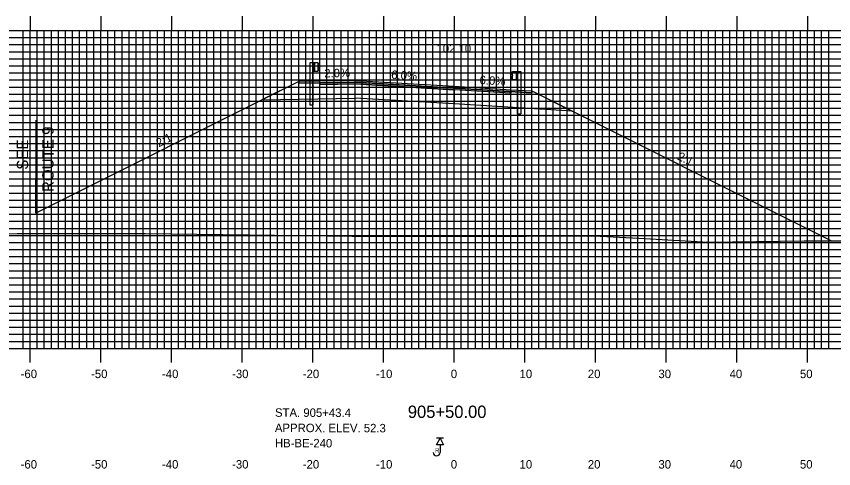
# Model space of a CAD drawing. Extents: x 857504 to 857847, y 364765 to 364985.
# Drawn here: x 857607.4 to 857723, y 364831.3 to 364895.3 of the extents above; entities that cross this region are included whole.
import ezdxf

# ---------------------------------------------------------------- set-up
doc = ezdxf.new("R2010")
doc.units = 0
for name, color, linetype in [('ANNOTATION', 7, 'Continuous'), ('BORING - REFUSAL', 7, 'Continuous'), ('D_Guardrail_Beam_Lt', 7, 'Continuous'), ('D_Guardrail_Beam_Rt', 7, 'Continuous'), ('D_Roadway_Centerline_Text', 7, 'Continuous'), ('D_Roadway_Edge_Shoulder', 7, 'Continuous'), ('D_Roadway_Edge_TW', 7, 'Continuous'), ('D_Roadway_Pavement', 7, 'Continuous'), ('D_Roadway_SlopeLines', 7, 'Continuous'), ('D_Roadway_SubGrade', 7, 'Continuous'), ('H_V ANNOTATION', 7, 'Continuous'), ('MAJOR', 7, 'Continuous'), ('MINOR', 7, 'Continuous'), ('S_Roadway_Centerline', 7, 'Continuous')]:
    doc.layers.add(name, color=color, linetype=linetype)

msp = doc.modelspace()

# ---------------------------------------------------------------- linework, layer by layer
at = {"layer": 'BORING - REFUSAL'}
for p, q in [((857667.79, 364835.6), (857666.83, 364835.6)), ((857667.31, 364834.64), (857667.31, 364833.58))]:
    msp.add_line(p, q, dxfattribs=at)
msp.add_lwpolyline([(857667.31, 364835.6), (857667.79, 364834.64), (857666.83, 364834.64)], close=True, dxfattribs=at)
msp.add_arc((857666.82, 364833.58), 0.485, 180, 0, dxfattribs=at)
at = {"layer": 'D_Guardrail_Beam_Lt'}
for p, q in [((857648.88, 364888.72), (857648.88, 364882.72)), ((857649.35, 364888.72), (857648.88, 364888.72)), ((857650.04, 364888.72), (857649.35, 364888.72)), ((857649.35, 364888.72), (857649.35, 364887.56)), ((857649.41, 364888.72), (857649.41, 364887.56)), ((857649.52, 364888.72), (857649.52, 364887.56)), ((857650.04, 364887.56), (857650.04, 364888.72)), ((857650.04, 364888.64), (857650.11, 364888.62)), ((857650.04, 364888.17), (857650.04, 364888.1)), ((857650.27, 364888.37), (857650.07, 364888.24)), ((857650.07, 364888.04), (857650.27, 364887.9)), ((857650.13, 364888.62), (857650.27, 364888.52)), ((857649.35, 364887.56), (857650.04, 364887.56)), ((857649.37, 364882.72), (857649.37, 364887.56)), ((857650.11, 364887.65), (857650.04, 364887.64)), ((857650.27, 364887.76), (857650.13, 364887.66)), ((857649.37, 364882.72), (857648.88, 364882.72)), ((857610.09, 364867.47), (857610.09, 364872.28))]:
    msp.add_line(p, q, dxfattribs=at)
for centre, major_axis, start_param, end_param in [((857650.12, 364888.17), (-0.0789, 0), 5.323254, 6.283185), ((857650.12, 364888.1), (-0.0789, 0), 6.283185, 7.243116), ((857650.1, 364888.58), (0.0417, 0), 0.959931, 1.376053), ((857650.22, 364888.45), (0.0877, 0), 5.323254, 7.243116), ((857650.1, 364887.69), (0.0417, 0), 4.907132, 5.323254), ((857650.22, 364887.83), (0.0877, 0), 5.323254, 7.243116)]:
    msp.add_ellipse(centre, major_axis=major_axis, ratio=0.995501, start_param=start_param, end_param=end_param, dxfattribs=at)
at = {"layer": 'D_Guardrail_Beam_Rt'}
for p, q in [((857677.49, 364887.4), (857677.35, 364887.3)), ((857677.35, 364887.15), (857677.54, 364887.02)), ((857677.54, 364886.82), (857677.35, 364886.68)), ((857677.58, 364887.42), (857677.5, 364887.4)), ((857677.57, 364886.95), (857677.57, 364886.88)), ((857677.58, 364887.5), (857678.27, 364887.5)), ((857677.58, 364886.34), (857677.58, 364887.5)), ((857678.1, 364887.5), (857678.1, 364886.34)), ((857678.2, 364887.5), (857678.2, 364886.34)), ((857678.27, 364887.5), (857678.74, 364887.5)), ((857678.27, 364887.5), (857678.27, 364886.34)), ((857678.74, 364887.5), (857678.74, 364881.5)), ((857677.35, 364886.54), (857677.49, 364886.44)), ((857677.5, 364886.43), (857677.58, 364886.42)), ((857678.27, 364886.34), (857677.58, 364886.34)), ((857678.25, 364881.5), (857678.25, 364886.34)), ((857678.25, 364881.5), (857678.74, 364881.5))]:
    msp.add_line(p, q, dxfattribs=at)
for centre, major_axis, start_param, end_param in [((857677.4, 364887.23), (-0.0877, 0), 5.323254, 7.243116), ((857677.51, 364887.36), (-0.0417, 0), 4.907132, 5.323254), ((857677.5, 364886.95), (0.0789, 0), 0, 0.959931), ((857677.5, 364886.88), (0.0789, 0), 5.323254, 6.283185), ((857677.4, 364886.61), (-0.0877, 0), 5.323254, 7.243116), ((857677.51, 364886.47), (-0.0417, 0), 0.959931, 1.376053)]:
    msp.add_ellipse(centre, major_axis=major_axis, ratio=0.995501, start_param=start_param, end_param=end_param, dxfattribs=at)
at = {"layer": 'D_Roadway_Edge_Shoulder'}
for points in [[(857655.31, 364886.24), (857650.31, 364886.14), (857650.31, 364886.14), (857647.31, 364886.08), (857647.31, 364885.83), (857650.31, 364885.89), (857655.31, 364885.99)], [(857669.31, 364885.4), (857677.31, 364884.92), (857677.31, 364884.92), (857680.31, 364884.74), (857680.31, 364884.49), (857669.31, 364885.15)]]:
    msp.add_lwpolyline(points, close=True, dxfattribs=at)
at = {"layer": 'D_Roadway_Edge_TW'}
msp.add_lwpolyline([(857655.31, 364886.24), (857669.31, 364885.4), (857669.31, 364885.15), (857655.31, 364885.99)], close=True, dxfattribs=at)
at = {"layer": 'D_Roadway_Pavement'}
for points in [[(857655.31, 364885.99), (857650.31, 364885.89), (857650.31, 364885.64), (857655.31, 364885.74)], [(857655.31, 364885.99), (857669.31, 364885.15), (857669.31, 364884.9), (857655.31, 364885.74)]]:
    msp.add_lwpolyline(points, close=True, dxfattribs=at)
for points in [[(857669.31, 364885.15), (857669.31, 364884.9)], [(857669.31, 364885.15), (857669.31, 364884.9)], [(857669.31, 364885.15), (857669.31, 364884.9)], [(857669.31, 364885.15), (857677.31, 364884.67), (857677.31, 364884.42), (857669.31, 364884.9)]]:
    msp.add_lwpolyline(points, dxfattribs=at)
at = {"layer": 'D_Roadway_SlopeLines'}
for points in [[(857647.31, 364886.08), (857610.09, 364867.47)], [(857680.31, 364884.74), (857722.71, 364863.54)]]:
    msp.add_lwpolyline(points, dxfattribs=at)
at = {"layer": 'D_Roadway_SubGrade'}
msp.add_line((857610.09, 364880.61), (857610.09, 364867.47), dxfattribs=at)
for points in [[(857655.31, 364885.74), (857650.31, 364885.64), (857650.31, 364885.89), (857647.31, 364885.83), (857647.31, 364886.08), (857642.1, 364883.47), (857655.31, 364883.74)], [(857655.31, 364885.74), (857669.31, 364884.9), (857669.31, 364882.9), (857655.31, 364883.74)], [(857669.31, 364884.9), (857669.31, 364885.15), (857680.31, 364884.49), (857680.31, 364884.74), (857685.99, 364881.9), (857669.31, 364882.9)]]:
    msp.add_lwpolyline(points, close=True, dxfattribs=at)
at = {"layer": 'MAJOR'}
for p, q in [((857609.31, 364895.31), (857609.31, 364893.3)), ((857619.31, 364895.31), (857619.31, 364893.3)), ((857629.31, 364895.31), (857629.31, 364893.3)), ((857639.31, 364895.31), (857639.31, 364893.3)), ((857649.31, 364895.31), (857649.31, 364893.3)), ((857659.31, 364895.31), (857659.31, 364893.3)), ((857669.31, 364895.31), (857669.31, 364893.3)), ((857679.31, 364895.31), (857679.31, 364893.3)), ((857689.31, 364895.31), (857689.31, 364893.3)), ((857699.31, 364895.31), (857699.31, 364893.3)), ((857709.31, 364895.31), (857709.31, 364893.3)), ((857719.31, 364895.31), (857719.31, 364893.3)), ((857529.31, 364893.3), (857809.31, 364893.3)), ((857529.31, 364893.3), (857809.31, 364893.3)), ((857609.31, 364848.3), (857609.31, 364893.3)), ((857619.31, 364848.3), (857619.31, 364893.3)), ((857629.31, 364848.3), (857629.31, 364893.3)), ((857639.31, 364848.3), (857639.31, 364893.3)), ((857649.31, 364848.3), (857649.31, 364893.3)), ((857659.31, 364848.3), (857659.31, 364893.3)), ((857669.31, 364848.3), (857669.31, 364893.3)), ((857679.31, 364848.3), (857679.31, 364893.3)), ((857689.31, 364848.3), (857689.31, 364893.3)), ((857699.31, 364848.3), (857699.31, 364893.3)), ((857709.31, 364848.3), (857709.31, 364893.3)), ((857719.31, 364848.3), (857719.31, 364893.3)), ((857529.31, 364888.3), (857809.31, 364888.3)), ((857529.31, 364883.3), (857809.31, 364883.3)), ((857529.31, 364878.3), (857809.31, 364878.3)), ((857529.31, 364873.3), (857809.31, 364873.3)), ((857529.31, 364868.3), (857809.31, 364868.3)), ((857529.31, 364863.3), (857809.31, 364863.3)), ((857529.31, 364858.3), (857809.31, 364858.3)), ((857529.31, 364853.3), (857809.31, 364853.3)), ((857529.31, 364848.3), (857809.31, 364848.3)), ((857529.31, 364848.3), (857809.31, 364848.3)), ((857609.31, 364846.3), (857609.31, 364848.3)), ((857619.31, 364846.3), (857619.31, 364848.3)), ((857629.31, 364846.3), (857629.31, 364848.3)), ((857639.31, 364846.3), (857639.31, 364848.3)), ((857649.31, 364846.3), (857649.31, 364848.3)), ((857659.31, 364846.3), (857659.31, 364848.3)), ((857669.31, 364846.3), (857669.31, 364848.3)), ((857679.31, 364846.3), (857679.31, 364848.3)), ((857689.31, 364846.3), (857689.31, 364848.3)), ((857699.31, 364846.3), (857699.31, 364848.3)), ((857709.31, 364846.3), (857709.31, 364848.3)), ((857719.31, 364846.3), (857719.31, 364848.3))]:
    msp.add_line(p, q, dxfattribs=at)
at = {"layer": 'MINOR'}
for p, q in [((857608.31, 364848.3), (857608.31, 364893.3)), ((857610.31, 364848.3), (857610.31, 364893.3)), ((857611.31, 364848.3), (857611.31, 364893.3)), ((857612.31, 364848.3), (857612.31, 364893.3)), ((857613.31, 364848.3), (857613.31, 364893.3)), ((857614.31, 364848.3), (857614.31, 364893.3)), ((857615.31, 364848.3), (857615.31, 364893.3)), ((857616.31, 364848.3), (857616.31, 364893.3)), ((857617.31, 364848.3), (857617.31, 364893.3)), ((857618.31, 364848.3), (857618.31, 364893.3)), ((857620.31, 364848.3), (857620.31, 364893.3)), ((857621.31, 364848.3), (857621.31, 364893.3)), ((857622.31, 364848.3), (857622.31, 364893.3)), ((857623.31, 364848.3), (857623.31, 364893.3)), ((857624.31, 364848.3), (857624.31, 364893.3)), ((857625.31, 364848.3), (857625.31, 364893.3)), ((857626.31, 364848.3), (857626.31, 364893.3)), ((857627.31, 364848.3), (857627.31, 364893.3)), ((857628.31, 364848.3), (857628.31, 364893.3)), ((857630.31, 364848.3), (857630.31, 364893.3)), ((857631.31, 364848.3), (857631.31, 364893.3)), ((857632.31, 364848.3), (857632.31, 364893.3)), ((857633.31, 364848.3), (857633.31, 364893.3)), ((857634.31, 364848.3), (857634.31, 364893.3)), ((857635.31, 364848.3), (857635.31, 364893.3)), ((857636.31, 364848.3), (857636.31, 364893.3)), ((857637.31, 364848.3), (857637.31, 364893.3)), ((857638.31, 364848.3), (857638.31, 364893.3)), ((857640.31, 364848.3), (857640.31, 364893.3)), ((857641.31, 364848.3), (857641.31, 364893.3)), ((857642.31, 364848.3), (857642.31, 364893.3)), ((857643.31, 364848.3), (857643.31, 364893.3)), ((857644.31, 364848.3), (857644.31, 364893.3)), ((857645.31, 364848.3), (857645.31, 364893.3)), ((857646.31, 364848.3), (857646.31, 364893.3)), ((857647.31, 364848.3), (857647.31, 364893.3)), ((857648.31, 364848.3), (857648.31, 364893.3)), ((857650.31, 364848.3), (857650.31, 364893.3)), ((857651.31, 364848.3), (857651.31, 364893.3)), ((857652.31, 364848.3), (857652.31, 364893.3)), ((857653.31, 364848.3), (857653.31, 364893.3)), ((857654.31, 364848.3), (857654.31, 364893.3)), ((857655.31, 364848.3), (857655.31, 364893.3)), ((857656.31, 364848.3), (857656.31, 364893.3)), ((857657.31, 364848.3), (857657.31, 364893.3)), ((857658.31, 364848.3), (857658.31, 364893.3)), ((857660.31, 364848.3), (857660.31, 364893.3)), ((857661.31, 364848.3), (857661.31, 364893.3)), ((857662.31, 364848.3), (857662.31, 364893.3)), ((857663.31, 364848.3), (857663.31, 364893.3)), ((857664.31, 364848.3), (857664.31, 364893.3)), ((857665.31, 364848.3), (857665.31, 364893.3)), ((857666.31, 364848.3), (857666.31, 364893.3)), ((857667.31, 364848.3), (857667.31, 364893.3)), ((857668.31, 364848.3), (857668.31, 364893.3)), ((857670.31, 364848.3), (857670.31, 364893.3)), ((857671.31, 364848.3), (857671.31, 364893.3)), ((857672.31, 364848.3), (857672.31, 364893.3)), ((857673.31, 364848.3), (857673.31, 364893.3)), ((857674.31, 364848.3), (857674.31, 364893.3)), ((857675.31, 364848.3), (857675.31, 364893.3)), ((857676.31, 364848.3), (857676.31, 364893.3)), ((857677.31, 364848.3), (857677.31, 364893.3)), ((857678.31, 364848.3), (857678.31, 364893.3)), ((857680.31, 364848.3), (857680.31, 364893.3)), ((857681.31, 364848.3), (857681.31, 364893.3)), ((857682.31, 364848.3), (857682.31, 364893.3)), ((857683.31, 364848.3), (857683.31, 364893.3)), ((857684.31, 364848.3), (857684.31, 364893.3)), ((857685.31, 364848.3), (857685.31, 364893.3)), ((857686.31, 364848.3), (857686.31, 364893.3)), ((857687.31, 364848.3), (857687.31, 364893.3)), ((857688.31, 364848.3), (857688.31, 364893.3)), ((857690.31, 364848.3), (857690.31, 364893.3)), ((857691.31, 364848.3), (857691.31, 364893.3)), ((857692.31, 364848.3), (857692.31, 364893.3)), ((857693.31, 364848.3), (857693.31, 364893.3)), ((857694.31, 364848.3), (857694.31, 364893.3)), ((857695.31, 364848.3), (857695.31, 364893.3)), ((857696.31, 364848.3), (857696.31, 364893.3)), ((857697.31, 364848.3), (857697.31, 364893.3)), ((857698.31, 364848.3), (857698.31, 364893.3)), ((857700.31, 364848.3), (857700.31, 364893.3)), ((857701.31, 364848.3), (857701.31, 364893.3)), ((857702.31, 364848.3), (857702.31, 364893.3)), ((857703.31, 364848.3), (857703.31, 364893.3)), ((857704.31, 364848.3), (857704.31, 364893.3)), ((857705.31, 364848.3), (857705.31, 364893.3)), ((857706.31, 364848.3), (857706.31, 364893.3)), ((857707.31, 364848.3), (857707.31, 364893.3)), ((857708.31, 364848.3), (857708.31, 364893.3)), ((857710.31, 364848.3), (857710.31, 364893.3)), ((857711.31, 364848.3), (857711.31, 364893.3)), ((857712.31, 364848.3), (857712.31, 364893.3)), ((857713.31, 364848.3), (857713.31, 364893.3)), ((857714.31, 364848.3), (857714.31, 364893.3)), ((857715.31, 364848.3), (857715.31, 364893.3)), ((857716.31, 364848.3), (857716.31, 364893.3)), ((857717.31, 364848.3), (857717.31, 364893.3)), ((857718.31, 364848.3), (857718.31, 364893.3)), ((857720.31, 364848.3), (857720.31, 364893.3)), ((857721.31, 364848.3), (857721.31, 364893.3)), ((857722.31, 364848.3), (857722.31, 364893.3)), ((857529.31, 364892.3), (857809.31, 364892.3)), ((857529.31, 364891.3), (857809.31, 364891.3)), ((857529.31, 364890.3), (857809.31, 364890.3)), ((857529.31, 364889.3), (857809.31, 364889.3)), ((857529.31, 364887.3), (857809.31, 364887.3)), ((857529.31, 364886.3), (857809.31, 364886.3)), ((857529.31, 364885.3), (857809.31, 364885.3)), ((857529.31, 364884.3), (857809.31, 364884.3)), ((857529.31, 364882.3), (857809.31, 364882.3)), ((857529.31, 364881.3), (857809.31, 364881.3)), ((857529.31, 364880.3), (857809.31, 364880.3)), ((857529.31, 364879.3), (857809.31, 364879.3)), ((857529.31, 364877.3), (857809.31, 364877.3)), ((857529.31, 364876.3), (857809.31, 364876.3)), ((857529.31, 364875.3), (857809.31, 364875.3)), ((857529.31, 364874.3), (857809.31, 364874.3)), ((857529.31, 364872.3), (857809.31, 364872.3)), ((857529.31, 364871.3), (857809.31, 364871.3)), ((857529.31, 364870.3), (857809.31, 364870.3)), ((857529.31, 364869.3), (857809.31, 364869.3)), ((857529.31, 364867.3), (857809.31, 364867.3)), ((857529.31, 364866.3), (857809.31, 364866.3)), ((857529.31, 364865.3), (857809.31, 364865.3)), ((857529.31, 364864.3), (857809.31, 364864.3)), ((857529.31, 364862.3), (857809.31, 364862.3)), ((857529.31, 364861.3), (857809.31, 364861.3)), ((857529.31, 364860.3), (857809.31, 364860.3)), ((857529.31, 364859.3), (857809.31, 364859.3)), ((857529.31, 364857.3), (857809.31, 364857.3)), ((857529.31, 364856.3), (857809.31, 364856.3)), ((857529.31, 364855.3), (857809.31, 364855.3)), ((857529.31, 364854.3), (857809.31, 364854.3)), ((857529.31, 364852.3), (857809.31, 364852.3)), ((857529.31, 364851.3), (857809.31, 364851.3)), ((857529.31, 364850.3), (857809.31, 364850.3)), ((857529.31, 364849.3), (857809.31, 364849.3))]:
    msp.add_line(p, q, dxfattribs=at)
at = {"layer": 'S_Roadway_Centerline'}
msp.add_lwpolyline([(857529.31, 364865.38), (857541.18, 364865.47), (857541.94, 364865.37), (857542.6, 364865.37), (857558.19, 364865.15), (857559.11, 364865.15), (857574.38, 364864.47), (857580.05, 364864.38), (857591.66, 364864.26), (857606.23, 364864.54), (857607.47, 364864.55), (857622.56, 364864.57), (857624, 364864.58), (857625.56, 364864.56), (857654.85, 364864.2), (857657.11, 364864.21), (857659.9, 364864.19), (857673.26, 364864.14), (857685.86, 364864.25), (857689.08, 364864.25), (857695.45, 364863.91), (857705.29, 364863.35), (857718.85, 364863.53), (857729.19, 364863.55)], dxfattribs=at)

# ---------------------------------------------------------------- texts
at = {"layer": 'ANNOTATION'}
for s, height, rotation, p in [('2.0%', 1.2, 1.1458, (857650.93, 364886.65)), ('6.0%', 1.2, 356.5664, (857660.37, 364886.47)), ('6.0%', 1.2, 356.5664, (857672.87, 364885.72)), ('ROUTE 9', 1.6, 90, (857612.62, 364870.44)), ('2:1', 1.2, 26.5651, (857627.5, 364876.77)), ('SEE', 1.6, 90, (857609.02, 364873.59)), ('2:1', 1.2, 333.4349, (857700.79, 364875.1))]:
    msp.add_text(s, height=height, rotation=rotation, dxfattribs=at).set_placement(p)
at = {"layer": 'BORING - REFUSAL'}
for s, p in [('STA. 905+43.4', (857643.95, 364838.63)), ('APPROX. ELEV. 52.3', (857643.94, 364836.47)), ('HB-BE-240', (857643.94, 364834.31))]:
    msp.add_text(s, height=1.2, rotation=359.8142, dxfattribs=at).set_placement(p)
msp.add_text('R', height=0.64, dxfattribs=at).set_placement((857666.6, 364833.53))
at = {"layer": 'D_Roadway_Centerline_Text'}
msp.add_text('102.10', height=1.2, dxfattribs=at).set_placement((857666.8, 364890.15))
at = {"layer": 'H_V ANNOTATION'}
for s, height, p in [('-60', 1.2, (857607.96, 364844.1)), ('-50', 1.2, (857617.92, 364844.1)), ('-40', 1.2, (857627.96, 364844.1)), ('-30', 1.2, (857637.88, 364844.1)), ('-20', 1.2, (857647.89, 364844.1)), ('-10', 1.2, (857658.24, 364844.1)), ('0', 1.2, (857668.83, 364844.1)), ('10', 1.2, (857678.56, 364844.1)), ('20', 1.2, (857688.22, 364844.1)), ('30', 1.2, (857698.21, 364844.1)), ('40', 1.2, (857708.28, 364844.1)), ('50', 1.2, (857718.24, 364844.1)), ('905+50.00', 1.75, (857662.75, 364838.46)), ('-60', 1.2, (857607.96, 364831.3)), ('-50', 1.2, (857617.92, 364831.3)), ('-40', 1.2, (857627.96, 364831.3)), ('-30', 1.2, (857637.88, 364831.3)), ('-20', 1.2, (857647.89, 364831.3)), ('-10', 1.2, (857658.24, 364831.3)), ('0', 1.2, (857668.83, 364831.3)), ('10', 1.2, (857678.56, 364831.3)), ('20', 1.2, (857688.22, 364831.3)), ('30', 1.2, (857698.21, 364831.3)), ('40', 1.2, (857708.28, 364831.3)), ('50', 1.2, (857718.24, 364831.3))]:
    msp.add_text(s, height=height, dxfattribs=at).set_placement(p)

doc.saveas('drawing.dxf')
